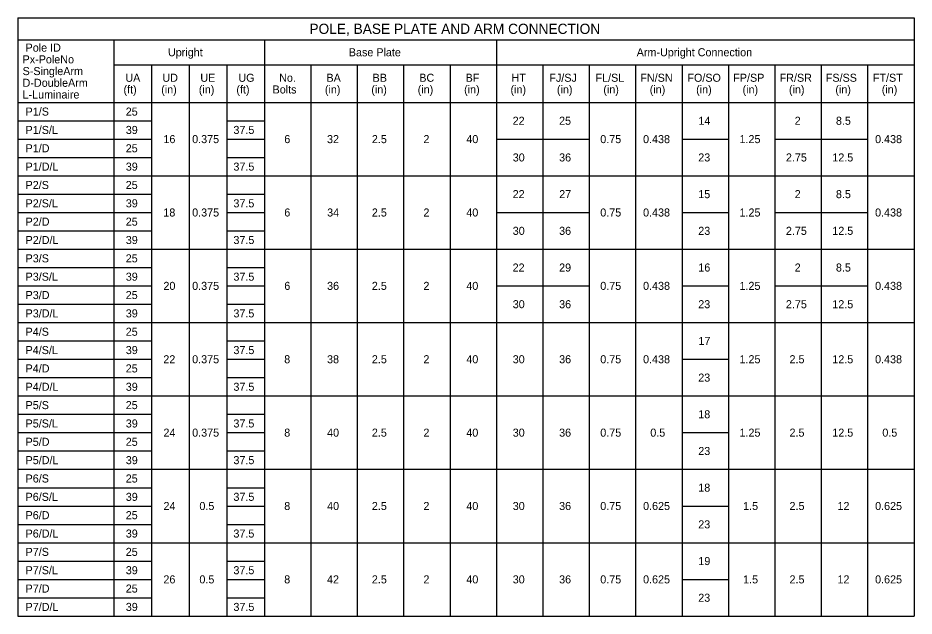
# Model space of a CAD drawing. Extents: x 0.9 to 14.1, y 0.6 to 9.3.
# Drawn here: x 6.35 to 14.14, y 4.14 to 9.34 of the extents above; entities that cross this region are included whole.
import ezdxf

# ---------------------------------------------------------------- set-up
doc = ezdxf.new("R2010")
doc.units = 0
for name, color, linetype in [('SumBoxBorder_dp', 7, 'Continuous'), ('SumBoxLines_dp', 7, 'Continuous'), ('TextLabel', 7, 'Continuous')]:
    doc.layers.add(name, color=color, linetype=linetype)

msp = doc.modelspace()

# ---------------------------------------------------------------- linework, layer by layer
at = {"layer": 'SumBoxBorder_dp'}
for p, q in [((6.345, 9.3443), (14.1396, 9.3443)), ((6.345, 9.3443), (6.345, 4.1392)), ((14.1396, 9.3443), (14.1396, 4.1392)), ((6.345, 9.1545), (14.1396, 9.1545)), ((6.345, 9.1545), (14.1396, 9.1545)), ((6.345, 4.1392), (14.1396, 4.1392))]:
    msp.add_line(p, q, dxfattribs=at)
at = {"layer": 'SumBoxLines_dp'}
for p, q in [((7.1796, 9.1545), (7.1796, 4.1392)), ((7.1796, 9.1545), (7.1796, 4.1392)), ((8.4887, 9.1545), (8.4887, 4.1392)), ((8.4887, 9.1545), (8.4887, 4.1392)), ((10.5069, 9.1545), (10.5069, 4.1392)), ((10.5069, 9.1545), (10.5069, 4.1392)), ((7.1796, 8.9363), (14.1396, 8.9363)), ((7.1796, 8.9363), (14.1396, 8.9363)), ((7.5069, 8.9363), (7.5069, 4.1392)), ((7.5069, 8.9363), (7.5069, 4.1392)), ((7.8341, 8.9363), (7.8341, 4.1392)), ((7.8341, 8.9363), (7.8341, 4.1392)), ((8.1614, 8.9363), (8.1614, 4.1392)), ((8.1614, 8.9363), (8.1614, 4.1392)), ((8.8923, 8.9363), (8.8923, 4.1392)), ((8.8923, 8.9363), (8.8923, 4.1392)), ((9.2959, 8.9363), (9.2959, 4.1392)), ((9.2959, 8.9363), (9.2959, 4.1392)), ((9.6996, 8.9363), (9.6996, 4.1392)), ((9.6996, 8.9363), (9.6996, 4.1392)), ((10.1032, 8.9363), (10.1032, 4.1392)), ((10.1032, 8.9363), (10.1032, 4.1392)), ((10.9105, 8.9363), (10.9105, 4.1392)), ((10.9105, 8.9363), (10.9105, 4.1392)), ((11.3141, 8.9363), (11.3141, 4.1392)), ((11.3141, 8.9363), (11.3141, 4.1392)), ((11.7178, 8.9363), (11.7178, 4.1392)), ((11.7178, 8.9363), (11.7178, 4.1392)), ((12.1214, 8.9363), (12.1214, 4.1392)), ((12.1214, 8.9363), (12.1214, 4.1392)), ((12.525, 8.9363), (12.525, 4.1392)), ((12.525, 8.9363), (12.525, 4.1392)), ((12.9287, 8.9363), (12.9287, 4.1392)), ((12.9287, 8.9363), (12.9287, 4.1392)), ((13.3323, 8.9363), (13.3323, 4.1392)), ((13.3323, 8.9363), (13.3323, 4.1392)), ((13.7359, 8.9363), (13.7359, 4.1392)), ((13.7359, 8.9363), (13.7359, 4.1392)), ((6.345, 8.609), (14.1396, 8.609)), ((6.345, 8.609), (14.1396, 8.609)), ((6.345, 8.4494), (7.5069, 8.4494)), ((6.345, 8.4494), (7.5069, 8.4494)), ((8.1614, 8.4494), (8.4887, 8.4494)), ((8.1614, 8.4494), (8.4887, 8.4494)), ((6.345, 8.2897), (7.5069, 8.2897)), ((6.345, 8.2897), (7.5069, 8.2897)), ((8.1614, 8.2897), (8.4887, 8.2897)), ((8.1614, 8.2897), (8.4887, 8.2897)), ((10.5069, 8.2897), (11.3141, 8.2897)), ((10.5069, 8.2897), (11.3141, 8.2897)), ((12.1214, 8.2897), (12.525, 8.2897)), ((12.1214, 8.2897), (12.525, 8.2897)), ((12.9287, 8.2897), (13.7359, 8.2897)), ((12.9287, 8.2897), (13.7359, 8.2897)), ((6.345, 8.1301), (7.5069, 8.1301)), ((6.345, 8.1301), (7.5069, 8.1301)), ((8.1614, 8.1301), (8.4887, 8.1301)), ((8.1614, 8.1301), (8.4887, 8.1301)), ((6.345, 7.9705), (14.1396, 7.9705)), ((6.345, 7.9705), (14.1396, 7.9705)), ((6.345, 7.8108), (7.5069, 7.8108)), ((6.345, 7.8108), (7.5069, 7.8108)), ((8.1614, 7.8108), (8.4887, 7.8108)), ((8.1614, 7.8108), (8.4887, 7.8108)), ((6.345, 7.6512), (7.5069, 7.6512)), ((6.345, 7.6512), (7.5069, 7.6512)), ((8.1614, 7.6512), (8.4887, 7.6512)), ((8.1614, 7.6512), (8.4887, 7.6512)), ((10.5069, 7.6512), (11.3141, 7.6512)), ((10.5069, 7.6512), (11.3141, 7.6512)), ((12.1214, 7.6512), (12.525, 7.6512)), ((12.1214, 7.6512), (12.525, 7.6512)), ((12.9287, 7.6512), (13.7359, 7.6512)), ((12.9287, 7.6512), (13.7359, 7.6512)), ((6.345, 7.4915), (7.5069, 7.4915)), ((6.345, 7.4915), (7.5069, 7.4915)), ((8.1614, 7.4915), (8.4887, 7.4915)), ((8.1614, 7.4915), (8.4887, 7.4915)), ((6.345, 7.3319), (14.1396, 7.3319)), ((6.345, 7.3319), (14.1396, 7.3319)), ((6.345, 7.1723), (7.5069, 7.1723)), ((6.345, 7.1723), (7.5069, 7.1723)), ((8.1614, 7.1723), (8.4887, 7.1723)), ((8.1614, 7.1723), (8.4887, 7.1723)), ((6.345, 7.0126), (7.5069, 7.0126)), ((6.345, 7.0126), (7.5069, 7.0126)), ((8.1614, 7.0126), (8.4887, 7.0126)), ((8.1614, 7.0126), (8.4887, 7.0126)), ((10.5069, 7.0126), (11.3141, 7.0126)), ((10.5069, 7.0126), (11.3141, 7.0126)), ((12.1214, 7.0126), (12.525, 7.0126)), ((12.1214, 7.0126), (12.525, 7.0126)), ((12.9287, 7.0126), (13.7359, 7.0126)), ((12.9287, 7.0126), (13.7359, 7.0126)), ((6.345, 6.853), (7.5069, 6.853)), ((6.345, 6.853), (7.5069, 6.853)), ((8.1614, 6.853), (8.4887, 6.853)), ((8.1614, 6.853), (8.4887, 6.853)), ((6.345, 6.6934), (14.1396, 6.6934)), ((6.345, 6.6934), (14.1396, 6.6934)), ((6.345, 6.5337), (7.5069, 6.5337)), ((6.345, 6.5337), (7.5069, 6.5337)), ((8.1614, 6.5337), (8.4887, 6.5337)), ((8.1614, 6.5337), (8.4887, 6.5337)), ((6.345, 6.3741), (7.5069, 6.3741)), ((6.345, 6.3741), (7.5069, 6.3741)), ((8.1614, 6.3741), (8.4887, 6.3741)), ((8.1614, 6.3741), (8.4887, 6.3741)), ((12.1214, 6.3741), (12.525, 6.3741)), ((12.1214, 6.3741), (12.525, 6.3741)), ((6.345, 6.2145), (7.5069, 6.2145)), ((6.345, 6.2145), (7.5069, 6.2145)), ((8.1614, 6.2145), (8.4887, 6.2145)), ((8.1614, 6.2145), (8.4887, 6.2145)), ((6.345, 6.0548), (14.1396, 6.0548)), ((6.345, 6.0548), (14.1396, 6.0548)), ((6.345, 5.8952), (7.5069, 5.8952)), ((6.345, 5.8952), (7.5069, 5.8952)), ((8.1614, 5.8952), (8.4887, 5.8952)), ((8.1614, 5.8952), (8.4887, 5.8952)), ((6.345, 5.7355), (7.5069, 5.7355)), ((6.345, 5.7355), (7.5069, 5.7355)), ((8.1614, 5.7355), (8.4887, 5.7355)), ((8.1614, 5.7355), (8.4887, 5.7355)), ((12.1214, 5.7355), (12.525, 5.7355)), ((12.1214, 5.7355), (12.525, 5.7355)), ((6.345, 5.5759), (7.5069, 5.5759)), ((6.345, 5.5759), (7.5069, 5.5759)), ((8.1614, 5.5759), (8.4887, 5.5759)), ((8.1614, 5.5759), (8.4887, 5.5759)), ((6.345, 5.4163), (14.1396, 5.4163)), ((6.345, 5.4163), (14.1396, 5.4163)), ((6.345, 5.2566), (7.5069, 5.2566)), ((6.345, 5.2566), (7.5069, 5.2566)), ((8.1614, 5.2566), (8.4887, 5.2566)), ((8.1614, 5.2566), (8.4887, 5.2566)), ((6.345, 5.097), (7.5069, 5.097)), ((6.345, 5.097), (7.5069, 5.097)), ((8.1614, 5.097), (8.4887, 5.097)), ((8.1614, 5.097), (8.4887, 5.097)), ((12.1214, 5.097), (12.525, 5.097)), ((12.1214, 5.097), (12.525, 5.097)), ((6.345, 4.9374), (7.5069, 4.9374)), ((6.345, 4.9374), (7.5069, 4.9374)), ((8.1614, 4.9374), (8.4887, 4.9374)), ((8.1614, 4.9374), (8.4887, 4.9374)), ((6.345, 4.7777), (14.1396, 4.7777)), ((6.345, 4.7777), (14.1396, 4.7777)), ((6.345, 4.6181), (7.5069, 4.6181)), ((6.345, 4.6181), (7.5069, 4.6181)), ((8.1614, 4.6181), (8.4887, 4.6181)), ((8.1614, 4.6181), (8.4887, 4.6181)), ((6.345, 4.4585), (7.5069, 4.4585)), ((6.345, 4.4585), (7.5069, 4.4585)), ((8.1614, 4.4585), (8.4887, 4.4585)), ((8.1614, 4.4585), (8.4887, 4.4585)), ((12.1214, 4.4585), (12.525, 4.4585)), ((12.1214, 4.4585), (12.525, 4.4585)), ((6.345, 4.2988), (7.5069, 4.2988)), ((6.345, 4.2988), (7.5069, 4.2988)), ((8.1614, 4.2988), (8.4887, 4.2988)), ((8.1614, 4.2988), (8.4887, 4.2988))]:
    msp.add_line(p, q, dxfattribs=at)

# ---------------------------------------------------------------- texts
at = {"layer": 'TextLabel'}
for s, height, p in [('POLE, BASE PLATE AND ARM CONNECTION', 0.089091, (8.8806, 9.2048)), ('  Pole ID', 0.07, (6.3596, 9.0507)), ('Upright', 0.07, (7.6503, 9.0104)), ('Base Plate', 0.07, (9.2231, 9.0104)), ('Arm-Upright Connection', 0.07, (11.727, 9.0104)), (' Px-PoleNo', 0.07, (6.3596, 8.9487)), (' S-SingleArm', 0.07, (6.3596, 8.8467)), (' D-DoubleArm', 0.07, (6.3596, 8.7447)), ('UA', 0.07, (7.2796, 8.7886)), ('UD', 0.07, (7.6015, 8.7886)), ('UE', 0.07, (7.9316, 8.7886)), ('UG', 0.07, (8.2625, 8.7886)), ('No.', 0.07, (8.6175, 8.7886)), ('BA', 0.07, (9.0287, 8.7886)), ('BB', 0.07, (9.43, 8.7886)), ('BC', 0.07, (9.8362, 8.7886)), ('BF', 0.07, (10.2391, 8.7886)), ('HT', 0.07, (10.638, 8.7886)), ('FJ/SJ', 0.07, (10.9673, 8.7886)), ('FL/SL', 0.07, (11.369, 8.7886)), ('FN/SN', 0.07, (11.7588, 8.7886)), ('FO/SO', 0.07, (12.1681, 8.7886)), ('FP/SP', 0.07, (12.5668, 8.7886)), ('FR/SR', 0.07, (12.9703, 8.7886)), ('FS/SS', 0.07, (13.3719, 8.7886)), ('FT/ST', 0.07, (13.7811, 8.7886)), ('(ft)', 0.07, (7.2633, 8.6866)), ('(in)', 0.07, (7.5913, 8.6866)), ('(in)', 0.07, (7.9186, 8.6866)), ('(ft)', 0.07, (8.2451, 8.6866)), ('Bolts', 0.07, (8.5599, 8.6866)), ('(in)', 0.07, (9.015, 8.6866)), ('(in)', 0.07, (9.4186, 8.6866)), ('(in)', 0.07, (9.8223, 8.6866)), ('(in)', 0.07, (10.2259, 8.6866)), ('(in)', 0.07, (10.6295, 8.6866)), ('(in)', 0.07, (11.0332, 8.6866)), ('(in)', 0.07, (11.4368, 8.6866)), ('(in)', 0.07, (11.8404, 8.6866)), ('(in)', 0.07, (12.2441, 8.6866)), ('(in)', 0.07, (12.6477, 8.6866)), ('(in)', 0.07, (13.0513, 8.6866)), ('(in)', 0.07, (13.455, 8.6866)), ('(in)', 0.07, (13.8586, 8.6866)), (' L-Luminaire', 0.07, (6.3596, 8.6427)), ('  P1/S', 0.07, (6.3596, 8.4942)), ('25', 0.07, (7.2827, 8.4942)), ('22', 0.07, (10.6479, 8.4144)), ('25', 0.07, (11.0518, 8.4144)), ('14', 0.07, (12.2638, 8.4144)), ('2', 0.07, (13.1011, 8.4144)), ('8.5', 0.07, (13.4599, 8.4144)), ('  P1/S/L', 0.07, (6.3596, 8.3345)), ('39', 0.07, (7.2832, 8.3345)), ('37.5', 0.07, (8.2193, 8.3345)), ('16', 0.07, (7.6105, 8.2547)), ('0.375', 0.07, (7.8606, 8.2547)), ('6', 0.07, (8.6619, 8.2547)), ('32', 0.07, (9.0334, 8.2547)), ('2.5', 0.07, (9.4235, 8.2547)), ('2', 0.07, (9.8721, 8.2547)), ('40', 0.07, (10.2451, 8.2547)), ('0.75', 0.07, (11.4102, 8.2547)), ('0.438', 0.07, (11.7824, 8.2547)), ('1.25', 0.07, (12.6212, 8.2547)), ('0.438', 0.07, (13.8005, 8.2547)), ('  P1/D', 0.07, (6.3596, 8.1749)), ('25', 0.07, (7.2827, 8.1749)), ('30', 0.07, (10.6488, 8.0951)), ('36', 0.07, (11.0523, 8.0951)), ('23', 0.07, (12.2624, 8.0951)), ('2.75', 0.07, (13.0248, 8.0951)), ('12.5', 0.07, (13.4284, 8.0951)), ('  P1/D/L', 0.07, (6.3596, 8.0153)), ('39', 0.07, (7.2832, 8.0153)), ('37.5', 0.07, (8.2193, 8.0153)), ('  P2/S', 0.07, (6.3596, 7.8556)), ('25', 0.07, (7.2827, 7.8556)), ('22', 0.07, (10.6479, 7.7758)), ('27', 0.07, (11.0531, 7.7758)), ('15', 0.07, (12.2627, 7.7758)), ('2', 0.07, (13.1011, 7.7758)), ('8.5', 0.07, (13.4599, 7.7758)), ('  P2/S/L', 0.07, (6.3596, 7.696)), ('39', 0.07, (7.2832, 7.696)), ('37.5', 0.07, (8.2193, 7.696)), ('18', 0.07, (7.6099, 7.6162)), ('0.375', 0.07, (7.8606, 7.6162)), ('6', 0.07, (8.6619, 7.6162)), ('34', 0.07, (9.0347, 7.6162)), ('2.5', 0.07, (9.4235, 7.6162)), ('2', 0.07, (9.8721, 7.6162)), ('40', 0.07, (10.2451, 7.6162)), ('0.75', 0.07, (11.4102, 7.6162)), ('0.438', 0.07, (11.7824, 7.6162)), ('1.25', 0.07, (12.6212, 7.6162)), ('0.438', 0.07, (13.8005, 7.6162)), ('  P2/D', 0.07, (6.3596, 7.5364)), ('25', 0.07, (7.2827, 7.5364)), ('30', 0.07, (10.6488, 7.4565)), ('36', 0.07, (11.0523, 7.4565)), ('23', 0.07, (12.2624, 7.4565)), ('2.75', 0.07, (13.0248, 7.4565)), ('12.5', 0.07, (13.4284, 7.4565)), ('  P2/D/L', 0.07, (6.3596, 7.3767)), ('39', 0.07, (7.2832, 7.3767)), ('37.5', 0.07, (8.2193, 7.3767)), ('  P3/S', 0.07, (6.3596, 7.2171)), ('25', 0.07, (7.2827, 7.2171)), ('22', 0.07, (10.6479, 7.1373)), ('29', 0.07, (11.0523, 7.1373)), ('16', 0.07, (12.2632, 7.1373)), ('2', 0.07, (13.1011, 7.1373)), ('8.5', 0.07, (13.4599, 7.1373)), ('  P3/S/L', 0.07, (6.3596, 7.0575)), ('39', 0.07, (7.2832, 7.0575)), ('37.5', 0.07, (8.2193, 7.0575)), ('20', 0.07, (7.6106, 6.9776)), ('0.375', 0.07, (7.8606, 6.9776)), ('6', 0.07, (8.6619, 6.9776)), ('36', 0.07, (9.0341, 6.9776)), ('2.5', 0.07, (9.4235, 6.9776)), ('2', 0.07, (9.8721, 6.9776)), ('40', 0.07, (10.2451, 6.9776)), ('0.75', 0.07, (11.4102, 6.9776)), ('0.438', 0.07, (11.7824, 6.9776)), ('1.25', 0.07, (12.6212, 6.9776)), ('0.438', 0.07, (13.8005, 6.9776)), ('  P3/D', 0.07, (6.3596, 6.8978)), ('25', 0.07, (7.2827, 6.8978)), ('30', 0.07, (10.6488, 6.818)), ('36', 0.07, (11.0523, 6.818)), ('23', 0.07, (12.2624, 6.818)), ('2.75', 0.07, (13.0248, 6.818)), ('12.5', 0.07, (13.4284, 6.818)), ('  P3/D/L', 0.07, (6.3596, 6.7382)), ('39', 0.07, (7.2832, 6.7382)), ('37.5', 0.07, (8.2193, 6.7382)), ('  P4/S', 0.07, (6.3596, 6.5785)), ('25', 0.07, (7.2827, 6.5785)), ('17', 0.07, (12.264, 6.4987)), ('  P4/S/L', 0.07, (6.3596, 6.4189)), ('39', 0.07, (7.2832, 6.4189)), ('37.5', 0.07, (8.2193, 6.4189)), ('22', 0.07, (7.6097, 6.3391)), ('0.375', 0.07, (7.8606, 6.3391)), ('8', 0.07, (8.6613, 6.3391)), ('38', 0.07, (9.0336, 6.3391)), ('2.5', 0.07, (9.4235, 6.3391)), ('2', 0.07, (9.8721, 6.3391)), ('40', 0.07, (10.2451, 6.3391)), ('30', 0.07, (10.6488, 6.3391)), ('36', 0.07, (11.0523, 6.3391)), ('0.75', 0.07, (11.4102, 6.3391)), ('0.438', 0.07, (11.7824, 6.3391)), ('1.25', 0.07, (12.6212, 6.3391)), ('2.5', 0.07, (13.0562, 6.3391)), ('12.5', 0.07, (13.4284, 6.3391)), ('0.438', 0.07, (13.8005, 6.3391)), ('  P4/D', 0.07, (6.3596, 6.2593)), ('25', 0.07, (7.2827, 6.2593)), ('23', 0.07, (12.2624, 6.1795)), ('  P4/D/L', 0.07, (6.3596, 6.0996)), ('39', 0.07, (7.2832, 6.0996)), ('37.5', 0.07, (8.2193, 6.0996)), ('  P5/S', 0.07, (6.3596, 5.94)), ('25', 0.07, (7.2827, 5.94)), ('18', 0.07, (12.2626, 5.8602)), ('  P5/S/L', 0.07, (6.3596, 5.7804)), ('39', 0.07, (7.2832, 5.7804)), ('37.5', 0.07, (8.2193, 5.7804)), ('24', 0.07, (7.6111, 5.7005)), ('0.375', 0.07, (7.8606, 5.7005)), ('8', 0.07, (8.6613, 5.7005)), ('40', 0.07, (9.0342, 5.7005)), ('2.5', 0.07, (9.4235, 5.7005)), ('2', 0.07, (9.8721, 5.7005)), ('40', 0.07, (10.2451, 5.7005)), ('30', 0.07, (10.6488, 5.7005)), ('36', 0.07, (11.0523, 5.7005)), ('0.75', 0.07, (11.4102, 5.7005)), ('0.5', 0.07, (11.8453, 5.7005)), ('1.25', 0.07, (12.6212, 5.7005)), ('2.5', 0.07, (13.0562, 5.7005)), ('12.5', 0.07, (13.4284, 5.7005)), ('0.5', 0.07, (13.8635, 5.7005)), ('  P5/D', 0.07, (6.3596, 5.6207)), ('25', 0.07, (7.2827, 5.6207)), ('  P5/D/L', 0.07, (6.3596, 5.4611)), ('23', 0.07, (12.2624, 5.5409)), ('39', 0.07, (7.2832, 5.4611)), ('37.5', 0.07, (8.2193, 5.4611)), ('  P6/S', 0.07, (6.3596, 5.3015)), ('25', 0.07, (7.2827, 5.3015)), ('18', 0.07, (12.2626, 5.2216)), ('  P6/S/L', 0.07, (6.3596, 5.1418)), ('39', 0.07, (7.2832, 5.1418)), ('37.5', 0.07, (8.2193, 5.1418)), ('24', 0.07, (7.6111, 5.062)), ('0.5', 0.07, (7.9235, 5.062)), ('8', 0.07, (8.6613, 5.062)), ('40', 0.07, (9.0342, 5.062)), ('2.5', 0.07, (9.4235, 5.062)), ('2', 0.07, (9.8721, 5.062)), ('40', 0.07, (10.2451, 5.062)), ('30', 0.07, (10.6488, 5.062)), ('36', 0.07, (11.0523, 5.062)), ('0.75', 0.07, (11.4102, 5.062)), ('0.625', 0.07, (11.7825, 5.062)), ('1.5', 0.07, (12.6526, 5.062)), ('2.5', 0.07, (13.0562, 5.062)), ('12', 0.07, (13.4734, 5.062)), ('0.625', 0.07, (13.8006, 5.062)), ('  P6/D', 0.07, (6.3596, 4.9822)), ('25', 0.07, (7.2827, 4.9822)), ('23', 0.07, (12.2624, 4.9024)), ('  P6/D/L', 0.07, (6.3596, 4.8225)), ('39', 0.07, (7.2832, 4.8225)), ('37.5', 0.07, (8.2193, 4.8225)), ('  P7/S', 0.07, (6.3596, 4.6629)), ('25', 0.07, (7.2827, 4.6629)), ('19', 0.07, (12.2632, 4.5831)), ('  P7/S/L', 0.07, (6.3596, 4.5033)), ('39', 0.07, (7.2832, 4.5033)), ('37.5', 0.07, (8.2193, 4.5033)), ('26', 0.07, (7.6105, 4.4235)), ('0.5', 0.07, (7.9235, 4.4235)), ('8', 0.07, (8.6613, 4.4235)), ('42', 0.07, (9.0334, 4.4235)), ('2.5', 0.07, (9.4235, 4.4235)), ('2', 0.07, (9.8721, 4.4235)), ('40', 0.07, (10.2451, 4.4235)), ('30', 0.07, (10.6488, 4.4235)), ('36', 0.07, (11.0523, 4.4235)), ('0.75', 0.07, (11.4102, 4.4235)), ('0.625', 0.07, (11.7825, 4.4235)), ('1.5', 0.07, (12.6526, 4.4235)), ('2.5', 0.07, (13.0562, 4.4235)), ('12', 0.07, (13.4734, 4.4235)), ('0.625', 0.07, (13.8006, 4.4235)), ('  P7/D', 0.07, (6.3596, 4.3436)), ('25', 0.07, (7.2827, 4.3436)), ('23', 0.07, (12.2624, 4.2638)), ('  P7/D/L', 0.07, (6.3596, 4.184)), ('39', 0.07, (7.2832, 4.184)), ('37.5', 0.07, (8.2193, 4.184))]:
    msp.add_text(s, height=height, dxfattribs=at).set_placement(p)

doc.saveas('drawing.dxf')
